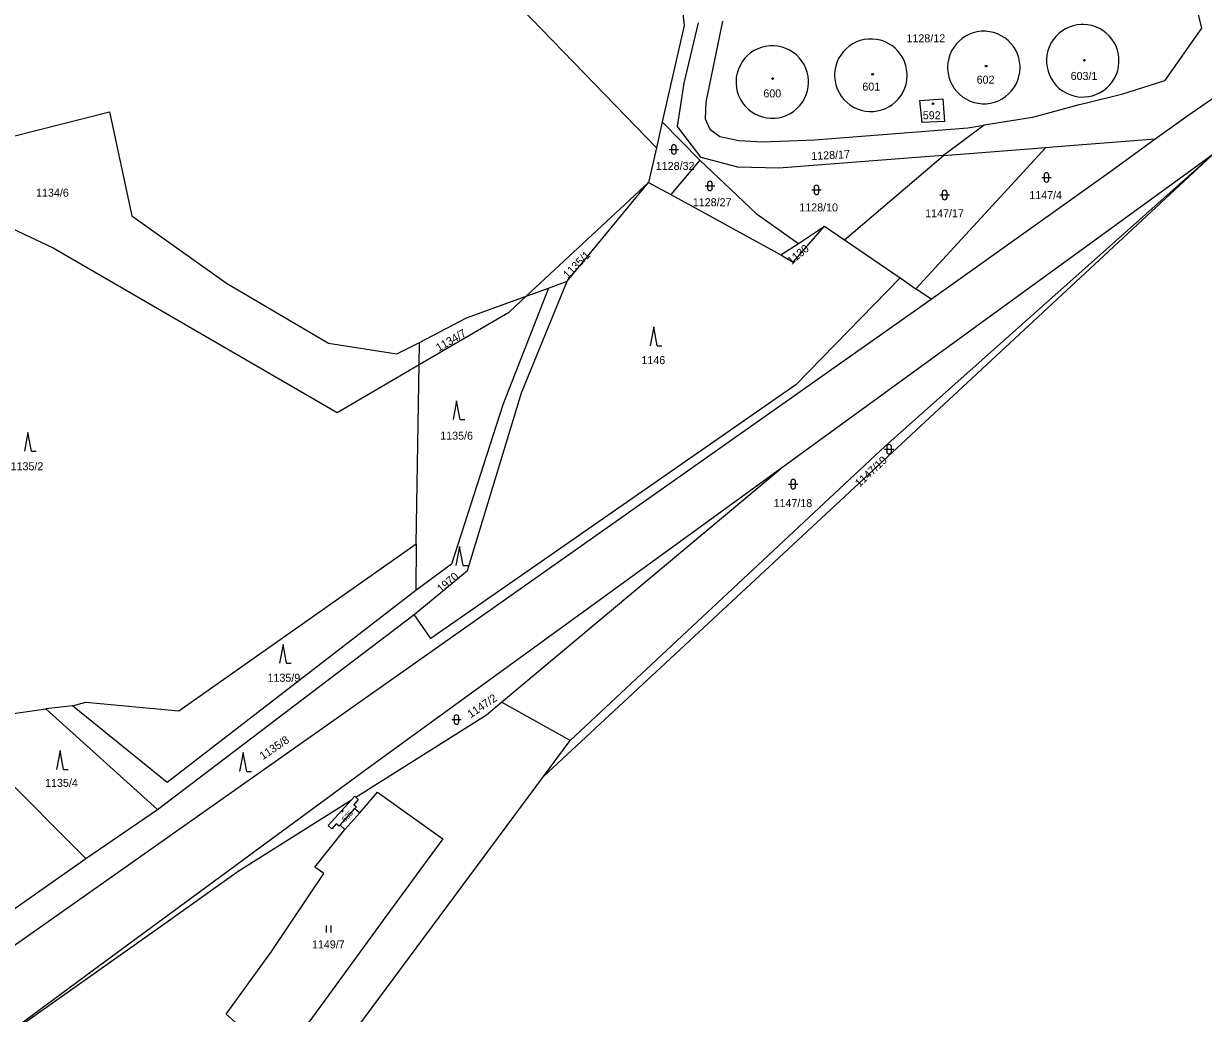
# Model space of a CAD drawing. Extents: x -794765 to -785424, y -1118958 to -1108731.
# Drawn here: x -787312.1 to -787061.6, y -1115964.7 to -1115754.6 of the extents above; entities that cross this region are included whole.
import ezdxf

# ---------------------------------------------------------------- set-up
doc = ezdxf.new("R2010")
doc.units = 0
for name, color, linetype in [('Level 66', 7, 'Continuous'), ('Level 75', 7, 'Continuous'), ('Level 76', 7, 'Continuous'), ('Level 77', 7, 'Continuous'), ('Level 79', 7, 'Continuous')]:
    doc.layers.add(name, color=color, linetype=linetype)

msp = doc.modelspace()

# ---------------------------------------------------------------- linework, layer by layer
at = {"layer": 'Level 66'}
for p, q in [((-787175.04, -1115781.31), (-787173.04, -1115781.31)), ((-787174.54, -1115780.81), (-787174.54, -1115781.81)), ((-787173.54, -1115781.81), (-787173.54, -1115780.81)), ((-787095.92, -1115787.26), (-787093.92, -1115787.26)), ((-787095.42, -1115786.76), (-787095.42, -1115787.76)), ((-787094.42, -1115787.76), (-787094.42, -1115786.76)), ((-787167.38, -1115789.06), (-787165.38, -1115789.06)), ((-787166.88, -1115788.56), (-787166.88, -1115789.56)), ((-787165.88, -1115789.56), (-787165.88, -1115788.56)), ((-787144.78, -1115789.9), (-787142.78, -1115789.9)), ((-787144.28, -1115789.4), (-787144.28, -1115790.4)), ((-787143.28, -1115790.4), (-787143.28, -1115789.4)), ((-787117.54, -1115790.98), (-787115.54, -1115790.98)), ((-787117.04, -1115790.48), (-787117.04, -1115791.48)), ((-787116.04, -1115791.48), (-787116.04, -1115790.48)), ((-787178.33, -1115818.98), (-787179.08, -1115822.98)), ((-787177.58, -1115822.98), (-787178.33, -1115818.98)), ((-787177.58, -1115822.98), (-787176.58, -1115822.98)), ((-787220.17, -1115834.66), (-787220.92, -1115838.66)), ((-787219.42, -1115838.66), (-787220.17, -1115834.66)), ((-787219.42, -1115838.66), (-787218.42, -1115838.66)), ((-787311.2, -1115841.37), (-787311.95, -1115845.37)), ((-787310.45, -1115845.37), (-787311.2, -1115841.37)), ((-787129.33, -1115844.95), (-787127.33, -1115844.95)), ((-787128.83, -1115844.45), (-787128.83, -1115845.45)), ((-787127.83, -1115845.45), (-787127.83, -1115844.45)), ((-787310.45, -1115845.37), (-787309.45, -1115845.37)), ((-787149.7, -1115852.36), (-787147.7, -1115852.36)), ((-787149.2, -1115851.86), (-787149.2, -1115852.86)), ((-787148.2, -1115852.86), (-787148.2, -1115851.86)), ((-787219.57, -1115865.62), (-787220.32, -1115869.62)), ((-787218.82, -1115869.62), (-787219.57, -1115865.62)), ((-787218.82, -1115869.62), (-787217.82, -1115869.62)), ((-787257.04, -1115886.36), (-787257.79, -1115890.36)), ((-787256.29, -1115890.36), (-787257.04, -1115886.36)), ((-787256.29, -1115890.36), (-787255.29, -1115890.36)), ((-787221.23, -1115902.32), (-787219.23, -1115902.32)), ((-787220.73, -1115901.82), (-787220.73, -1115902.82)), ((-787219.73, -1115902.82), (-787219.73, -1115901.82)), ((-787304.4, -1115908.91), (-787305.15, -1115912.91)), ((-787303.65, -1115912.91), (-787304.4, -1115908.91)), ((-787265.5, -1115909.32), (-787266.25, -1115913.32)), ((-787264.75, -1115913.32), (-787265.5, -1115909.32)), ((-787303.65, -1115912.91), (-787302.65, -1115912.91)), ((-787264.75, -1115913.32), (-787263.75, -1115913.32)), ((-787247.81, -1115947.52), (-787247.81, -1115946.02)), ((-787246.81, -1115947.52), (-787246.81, -1115946.02))]:
    msp.add_line(p, q, dxfattribs=at)
for centre, start, end in [((-787174.04, -1115780.81), 0, 180), ((-787174.04, -1115781.81), 180, 359.9879), ((-787094.92, -1115786.76), 0, 180), ((-787166.38, -1115788.56), 0, 180), ((-787166.38, -1115789.56), 180, 359.9879), ((-787143.78, -1115789.4), 0, 180), ((-787094.92, -1115787.76), 180, 359.9879), ((-787143.78, -1115790.4), 180, 359.9879), ((-787116.54, -1115790.48), 0, 180), ((-787116.54, -1115791.48), 180, 359.9879), ((-787128.33, -1115844.45), 0, 180), ((-787128.33, -1115845.45), 180, 359.9879), ((-787148.7, -1115851.86), 0, 180), ((-787148.7, -1115852.86), 180, 359.9879), ((-787220.23, -1115901.82), 0, 180), ((-787220.23, -1115902.82), 180, 359.9879)]:
    msp.add_arc(centre, 0.5, start, end, dxfattribs=at)
at = {"layer": 'Level 75'}
for p, q in [((-787220.86, -1115736.4), (-787177.74, -1115780.94)), ((-787171.89, -1115767.27), (-787168.84, -1115754.42)), ((-787176.5, -1115775.47), (-787177.74, -1115780.94)), ((-787176.5, -1115775.47), (-787168.56, -1115783.62)), ((-787108.15, -1115776.16), (-787116.77, -1115782.58)), ((-787081.26, -1115785.9), (-787071.85, -1115779.08)), ((-787177.74, -1115780.94), (-787179.4, -1115788.31)), ((-787122.63, -1115810.87), (-787095.05, -1115780.88)), ((-787116.77, -1115782.58), (-787095.05, -1115780.88)), ((-787059.63, -1115782.48), (-787201.76, -1115914.44)), ((-787168.56, -1115783.62), (-787174.66, -1115790.91)), ((-787059.63, -1115782.48), (-787151.42, -1115849.12)), ((-787137.82, -1115800.52), (-787116.77, -1115782.58)), ((-787116.77, -1115782.58), (-787119.77, -1115782.81)), ((-787119.38, -1115813.08), (-787081.26, -1115785.9)), ((-787179.4, -1115788.31), (-787205.38, -1115812.43)), ((-787196.73, -1115809.3), (-787179.4, -1115788.31)), ((-787179.4, -1115788.31), (-787174.66, -1115790.91)), ((-787174.66, -1115790.91), (-787151.32, -1115803.7)), ((-787147.59, -1115801.26), (-787142.06, -1115797.63)), ((-787142.06, -1115797.63), (-787137.82, -1115800.52)), ((-787151.32, -1115803.7), (-787147.59, -1115801.26)), ((-787137.82, -1115800.52), (-787126, -1115808.57)), ((-787200.67, -1115810.73), (-787196.73, -1115809.3)), ((-787126, -1115808.57), (-787122.63, -1115810.87)), ((-787205.38, -1115812.43), (-787200.67, -1115810.73)), ((-787119.38, -1115813.08), (-787122.63, -1115810.87)), ((-787317.55, -1115952.64), (-787119.38, -1115813.08)), ((-787228.11, -1115826.95), (-787228.03, -1115822.3)), ((-787228.8, -1115864.99), (-787228.11, -1115826.95)), ((-787210.62, -1115898.66), (-787151.42, -1115849.12)), ((-787228.8, -1115864.99), (-787228.84, -1115874.95)), ((-787283.72, -1115921.39), (-787229.17, -1115880.05)), ((-787327.71, -1115902.99), (-787307.38, -1115900.03)), ((-787301.75, -1115899.41), (-787307.38, -1115900.03)), ((-787307.38, -1115900.03), (-787283.72, -1115921.39)), ((-787196.06, -1115906.75), (-787210.62, -1115898.66)), ((-787327.71, -1115902.99), (-787298.9, -1115931.82)), ((-787201.76, -1115914.44), (-787196.06, -1115906.75)), ((-787241.6, -1115918.78), (-787235.67, -1115915.05)), ((-787266.56, -1115934.47), (-787242.53, -1115919.36)), ((-787247.48, -1115924.81), (-787242.53, -1115919.36)), ((-787241.6, -1115918.78), (-787241.07, -1115919.28)), ((-787298.9, -1115931.82), (-787283.72, -1115921.39)), ((-787243.91, -1115925.68), (-787240.72, -1115922.12)), ((-787315.11, -1115943.23), (-787298.9, -1115931.82))]:
    msp.add_line(p, q, dxfattribs=at)
for points in [[(-787184.41, -1115660.66), (-787181.96, -1115662.41), (-787171.87, -1115755), (-787176.5, -1115775.47)], [(-787069.54, -1115723.37), (-787068.64, -1115727.49), (-787066.22, -1115738.58), (-787065.45, -1115741.57), (-787061.97, -1115755.56), (-787069.88, -1115766.77)], [(-787163.75, -1115754.05), (-787167.29, -1115771.29), (-787167.39, -1115774.8), (-787166.42, -1115777), (-787164.3, -1115778.58), (-787160.26, -1115779.44), (-787155.23, -1115779.72), (-787144.09, -1115779.24), (-787111.63, -1115776.72), (-787108.15, -1115776.16)], [(-787094.89, -1115763.01), (-787094.78, -1115763.88), (-787094.57, -1115764.73), (-787094.27, -1115765.56), (-787093.87, -1115766.34), (-787093.39, -1115767.07), (-787092.83, -1115767.75), (-787092.19, -1115768.35), (-787091.49, -1115768.88), (-787090.73, -1115769.32), (-787089.93, -1115769.68), (-787089.1, -1115769.94), (-787088.23, -1115770.11), (-787087.36, -1115770.18), (-787086.88, -1115770.17), (-787086.01, -1115770.08), (-787085.15, -1115769.9), (-787084.32, -1115769.61), (-787083.52, -1115769.24), (-787082.78, -1115768.77), (-787082.09, -1115768.23), (-787081.47, -1115767.61), (-787080.92, -1115766.92), (-787080.46, -1115766.18), (-787080.08, -1115765.39), (-787079.8, -1115764.56), (-787079.61, -1115763.7), (-787079.52, -1115762.83), (-787079.53, -1115761.95), (-787079.64, -1115761.08), (-787079.85, -1115760.23), (-787080.15, -1115759.4), (-787080.55, -1115758.62), (-787081.03, -1115757.89), (-787081.59, -1115757.22), (-787082.23, -1115756.61), (-787082.93, -1115756.08), (-787083.69, -1115755.64), (-787084.49, -1115755.28), (-787085.32, -1115755.02), (-787086.19, -1115754.85), (-787087.06, -1115754.78), (-787087.54, -1115754.79), (-787088.42, -1115754.88), (-787089.27, -1115755.06), (-787090.1, -1115755.35), (-787090.9, -1115755.72), (-787091.64, -1115756.19), (-787092.33, -1115756.73), (-787092.95, -1115757.35), (-787093.5, -1115758.04), (-787093.96, -1115758.78), (-787094.34, -1115759.57), (-787094.62, -1115760.4), (-787094.81, -1115761.26), (-787094.9, -1115762.13), (-787094.89, -1115763.01)], [(-787107.69, -1115771.6), (-787106.82, -1115771.49), (-787105.97, -1115771.28), (-787105.14, -1115770.98), (-787104.36, -1115770.58), (-787103.63, -1115770.1), (-787102.96, -1115769.54), (-787102.35, -1115768.9), (-787101.82, -1115768.2), (-787101.38, -1115767.45), (-787101.02, -1115766.64), (-787100.76, -1115765.81), (-787100.59, -1115764.94), (-787100.52, -1115764.07), (-787100.53, -1115763.59), (-787100.62, -1115762.71), (-787100.8, -1115761.86), (-787101.09, -1115761.03), (-787101.46, -1115760.23), (-787101.93, -1115759.49), (-787102.47, -1115758.8), (-787103.09, -1115758.18), (-787103.78, -1115757.63), (-787104.52, -1115757.17), (-787105.31, -1115756.79), (-787106.14, -1115756.51), (-787107, -1115756.32), (-787107.87, -1115756.23), (-787108.75, -1115756.24), (-787109.62, -1115756.35), (-787110.47, -1115756.56), (-787111.3, -1115756.86), (-787112.08, -1115757.26), (-787112.81, -1115757.74), (-787113.48, -1115758.3), (-787114.09, -1115758.94), (-787114.62, -1115759.64), (-787115.06, -1115760.4), (-787115.42, -1115761.2), (-787115.68, -1115762.03), (-787115.85, -1115762.9), (-787115.92, -1115763.77), (-787115.91, -1115764.25), (-787115.82, -1115765.13), (-787115.64, -1115765.98), (-787115.35, -1115766.81), (-787114.98, -1115767.61), (-787114.52, -1115768.35), (-787113.97, -1115769.04), (-787113.35, -1115769.66), (-787112.66, -1115770.21), (-787111.92, -1115770.67), (-787111.13, -1115771.05), (-787110.3, -1115771.33), (-787109.44, -1115771.52), (-787108.57, -1115771.61), (-787107.69, -1115771.6)], [(-787152.63, -1115774.68), (-787151.76, -1115774.57), (-787150.91, -1115774.36), (-787150.08, -1115774.06), (-787149.3, -1115773.66), (-787148.57, -1115773.18), (-787147.9, -1115772.62), (-787147.29, -1115771.98), (-787146.76, -1115771.28), (-787146.32, -1115770.52), (-787145.96, -1115769.72), (-787145.7, -1115768.89), (-787145.53, -1115768.02), (-787145.46, -1115767.15), (-787145.47, -1115766.67), (-787145.56, -1115765.79), (-787145.74, -1115764.94), (-787146.03, -1115764.11), (-787146.4, -1115763.31), (-787146.86, -1115762.57), (-787147.41, -1115761.88), (-787148.03, -1115761.26), (-787148.72, -1115760.71), (-787149.46, -1115760.25), (-787150.25, -1115759.87), (-787151.08, -1115759.59), (-787151.94, -1115759.4), (-787152.81, -1115759.31), (-787153.69, -1115759.32), (-787154.56, -1115759.43), (-787155.41, -1115759.64), (-787156.23, -1115759.95), (-787157.02, -1115760.34), (-787157.75, -1115760.83), (-787158.42, -1115761.39), (-787159.03, -1115762.03), (-787159.55, -1115762.73), (-787160, -1115763.48), (-787160.35, -1115764.29), (-787160.62, -1115765.12), (-787160.78, -1115765.99), (-787160.85, -1115766.86), (-787160.84, -1115767.32), (-787160.76, -1115768.19), (-787160.57, -1115769.05), (-787160.29, -1115769.88), (-787159.91, -1115770.68), (-787159.45, -1115771.42), (-787158.91, -1115772.11), (-787158.29, -1115772.73), (-787157.6, -1115773.28), (-787156.86, -1115773.75), (-787156.07, -1115774.12), (-787155.24, -1115774.41), (-787154.38, -1115774.6), (-787153.51, -1115774.69), (-787152.63, -1115774.68)], [(-787132.74, -1115757.88), (-787133.61, -1115757.99), (-787134.46, -1115758.2), (-787135.29, -1115758.5), (-787136.07, -1115758.9), (-787136.8, -1115759.38), (-787137.47, -1115759.94), (-787138.08, -1115760.58), (-787138.61, -1115761.28), (-787139.05, -1115762.03), (-787139.41, -1115762.84), (-787139.67, -1115763.67), (-787139.84, -1115764.54), (-787139.91, -1115765.41), (-787139.9, -1115765.89), (-787139.81, -1115766.77), (-787139.63, -1115767.62), (-787139.34, -1115768.45), (-787138.97, -1115769.25), (-787138.51, -1115769.99), (-787137.96, -1115770.68), (-787137.34, -1115771.3), (-787136.65, -1115771.85), (-787135.91, -1115772.31), (-787135.12, -1115772.69), (-787134.29, -1115772.97), (-787133.43, -1115773.16), (-787132.56, -1115773.25), (-787131.68, -1115773.24), (-787130.81, -1115773.13), (-787129.96, -1115772.92), (-787129.13, -1115772.62), (-787128.35, -1115772.22), (-787127.62, -1115771.74), (-787126.95, -1115771.18), (-787126.34, -1115770.54), (-787125.81, -1115769.84), (-787125.37, -1115769.08), (-787125.01, -1115768.28), (-787124.75, -1115767.45), (-787124.58, -1115766.58), (-787124.51, -1115765.71), (-787124.52, -1115765.23), (-787124.61, -1115764.35), (-787124.79, -1115763.5), (-787125.08, -1115762.67), (-787125.45, -1115761.87), (-787125.92, -1115761.13), (-787126.46, -1115760.44), (-787127.08, -1115759.82), (-787127.77, -1115759.27), (-787128.51, -1115758.81), (-787129.3, -1115758.43), (-787130.13, -1115758.15), (-787130.99, -1115757.96), (-787131.86, -1115757.87), (-787132.74, -1115757.88)], [(-787071.85, -1115779.08), (-787064.93, -1115774.13), (-787045, -1115760.38)], [(-787119.77, -1115782.81), (-787151.73, -1115785.29), (-787160.49, -1115785.09), (-787168.25, -1115783.03), (-787173.24, -1115776.41), (-787171.89, -1115767.27)], [(-787069.88, -1115766.77), (-787079, -1115769.63), (-787086.39, -1115771.47), (-787088.25, -1115771.93), (-787097.91, -1115774.52), (-787108.15, -1115776.16)], [(-787116.57, -1115775.38), (-787121.35, -1115775.6), (-787121.82, -1115770.9), (-787116.96, -1115770.57), (-787116.57, -1115775.38)], [(-787404.53, -1115807.78), (-787390.18, -1115802.19), (-787391.44, -1115798.03), (-787293.88, -1115773.33), (-787289.16, -1115795.37), (-787269.06, -1115809.66), (-787247.4, -1115822.4), (-787232.85, -1115824.7), (-787228.03, -1115822.3)], [(-787095.05, -1115780.88), (-787093.58, -1115780.77), (-787071.85, -1115779.08)], [(-787196.06, -1115906.75), (-787129.19, -1115844.27), (-787059.63, -1115782.48)], [(-787168.56, -1115783.62), (-787156.57, -1115794.9), (-787147.59, -1115801.26)], [(-787402.4, -1115818.5), (-787387.6, -1115816.07), (-787386.97, -1115811.59), (-787335.05, -1115789.4), (-787319.32, -1115795.93), (-787305.87, -1115802.19), (-787245.53, -1115837.12), (-787228.11, -1115826.95)], [(-787151.32, -1115803.7), (-787148.72, -1115805.23), (-787142.06, -1115797.63)], [(-787126, -1115808.57), (-787148.11, -1115831.24), (-787225.66, -1115885.11), (-787229.17, -1115880.05)], [(-787229.17, -1115880.05), (-787217.85, -1115870.69), (-787206.39, -1115832.97), (-787196.73, -1115809.3)], [(-787200.67, -1115810.73), (-787210.37, -1115835.49), (-787221.28, -1115869.34), (-787228.84, -1115874.95)], [(-787228.11, -1115826.95), (-787208.97, -1115815.77), (-787205.38, -1115812.43)], [(-787228.03, -1115822.3), (-787218.07, -1115817.03), (-787205.38, -1115812.43)], [(-787151.42, -1115849.12), (-787238.95, -1115912.66), (-787295.97, -1115954.55), (-787318.53, -1115971.13), (-787318.47, -1115971.25)], [(-787301.75, -1115899.41), (-787298.93, -1115898.62), (-787279.15, -1115900.5), (-787228.8, -1115864.99)], [(-787228.84, -1115874.95), (-787281.64, -1115915.68), (-787301.75, -1115899.41)], [(-787235.67, -1115915.05), (-787213.86, -1115901.34), (-787210.62, -1115898.66)], [(-787258.17, -1116021.36), (-787255.6, -1115987.01), (-787201.76, -1115914.44)], [(-787240.72, -1115922.12), (-787237, -1115917.73), (-787223.14, -1115927.61), (-787235.24, -1115944.1), (-787247.33, -1115960.77), (-787257.7, -1115974.98), (-787269.1, -1115964.84), (-787259.46, -1115951.54), (-787248.4, -1115934.98), (-787250.3, -1115933.62), (-787243.91, -1115925.68)], [(-787242.53, -1115919.36), (-787241.81, -1115918.57), (-787241.6, -1115918.78)], [(-787241.07, -1115919.28), (-787242.02, -1115920.39), (-787241.42, -1115920.82), (-787241.76, -1115921.19), (-787240.72, -1115922.12)], [(-787243.91, -1115925.68), (-787244.94, -1115924.75), (-787245.14, -1115924.96), (-787245.74, -1115924.49), (-787246.66, -1115925.53), (-787247.48, -1115924.81)], [(-787318.47, -1115971.25), (-787282.37, -1115945.72), (-787266.56, -1115934.47)]]:
    msp.add_lwpolyline(points, dxfattribs=at)
at = {"layer": 'Level 77'}
msp.add_line((-787244.94, -1115924.75), (-787241.76, -1115921.19), dxfattribs=at)
at = {"layer": 'Level 79'}
for centre, radius in [((-787086.87, -1115762.37), 0.175), ((-787107.73, -1115763.63), 0.175), ((-787153.08, -1115766.27), 0.175), ((-787131.85, -1115765.37), 0.175), ((-787119.03, -1115771.62), 0.175), ((-787244.4, -1115921.77), 0.117)]:
    msp.add_circle(centre, radius, dxfattribs=at)

# ---------------------------------------------------------------- texts
at = {"layer": 'Level 76'}
for s, p in [('1128/12', (-787124.65, -1115758.57)), ('603/1', (-787089.79, -1115766.56)), ('601', (-787134.02, -1115768.82)), ('602', (-787109.75, -1115767.35)), ('600', (-787155.04, -1115770.27)), ('592', (-787121.19, -1115774.9)), ('1128/32', (-787177.88, -1115785.66)), ('1134/6', (-787309.49, -1115791.34)), ('1128/27', (-787170.02, -1115793.37)), ('1147/4', (-787098.57, -1115791.85)), ('1128/10', (-787147.41, -1115794.46)), ('1147/17', (-787120.68, -1115795.71)), ('1146', (-787180.93, -1115826.88)), ('1135/6', (-787223.66, -1115842.92)), ('1135/2', (-787314.89, -1115849.41)), ('1147/18', (-787152.88, -1115857.23)), ('1135/9', (-787260.34, -1115894.3)), ('1135/4', (-787307.57, -1115916.61)), ('1149/7', (-787250.9, -1115950.89))]:
    msp.add_text(s, height=1.7, dxfattribs=at).set_placement(p)
for s, height, rotation, p in [('1128/17', 1.7, 3, (-787144.82, -1115783.57)), ('1130', 1.7, 40, (-787149.06, -1115805.89)), ('1135/1', 1.7, 45, (-787196.56, -1115808.81)), ('1134/7', 1.7, 30, (-787223.97, -1115824.28)), ('1147/19', 1.7, 43, (-787134.63, -1115853.09)), ('1970', 1.7, 40, (-787223.47, -1115875.47)), ('1147/2', 1.7, 34, (-787217.18, -1115902.07)), ('1135/8', 1.7, 34, (-787261.31, -1115910.94)), ('635', 1.14, 47, (-787243.88, -1115924.17))]:
    msp.add_text(s, height=height, rotation=rotation, dxfattribs=at).set_placement(p)

doc.saveas('drawing.dxf')
